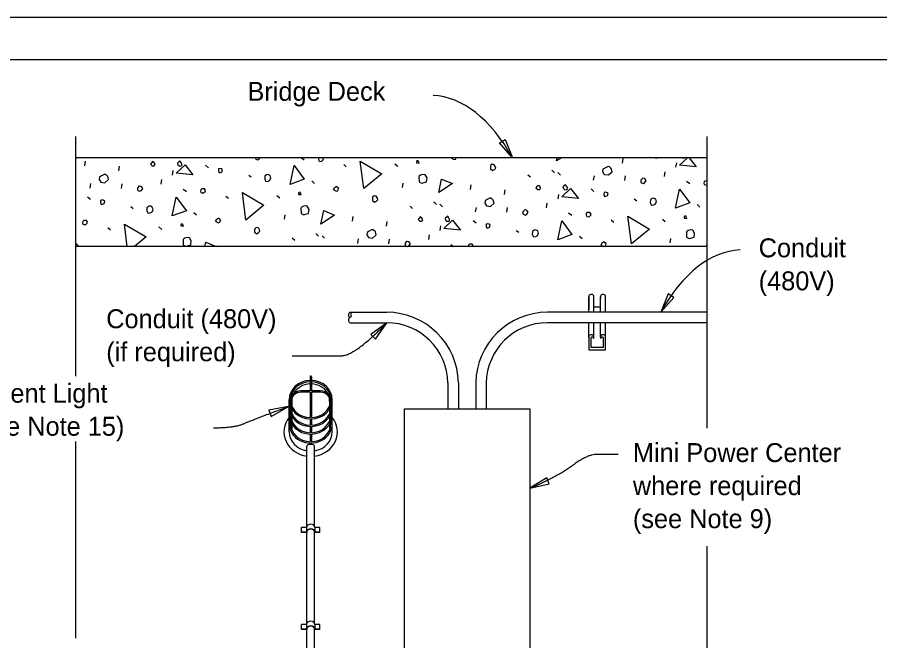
# Model space of a CAD drawing. Extents: x 0 to 30.8, y 0 to 21.2.
# Drawn here: x 12.47 to 19.36, y 14.82 to 19.8 of the extents above; entities that cross this region are included whole.
import ezdxf

# ---------------------------------------------------------------- set-up
doc = ezdxf.new("R2010")
doc.units = 0
for name, color, linetype in [('ActivePts-ConstElements', 7, 'Continuous'), ('Dimension', 7, 'Continuous'), ('Lighting', 7, 'Continuous'), ('Miscellaneous', 7, 'Continuous'), ('Miscellaneous1', 7, 'Continuous'), ('SteelGirder', 7, 'Continuous'), ('SupstrConc', 7, 'Continuous'), ('TextStructures', 7, 'Continuous')]:
    doc.layers.add(name, color=color, linetype=linetype)

msp = doc.modelspace()

# ---------------------------------------------------------------- linework, layer by layer
at = {"layer": 'ActivePts-ConstElements'}
msp.add_lwpolyline([(0, 0), (30.7879, 0), (30.7879, 19.4596), (0, 19.4596)], close=True, dxfattribs=at)
at = {"layer": 'Dimension'}
for points in [[(12.9354, 16.9316), (12.9354, 18.846)], [(17.9781, 16.5154), (17.9781, 18.846)], [(12.9354, 14.8369), (12.9354, 16.4094)], [(17.9781, 9.9617), (17.9781, 14.3999), (17.9006, 14.3999), (17.9781, 14.4336), (18.0556, 14.4674), (17.9781, 14.4674), (17.9781, 15.572)]]:
    msp.add_lwpolyline(points, dxfattribs=at)
for points in [[(16.4238, 18.6763), (16.3192, 18.7952), (16.3642, 18.8231)], [(17.6075, 17.442), (17.7122, 17.561), (17.6672, 17.5888)], [(15.4188, 17.3588), (15.2914, 17.2647), (15.3295, 17.228)], [(14.6337, 16.6891), (14.478, 16.6599), (14.4963, 16.6102)], [(16.563, 16.0355), (16.7173, 16.0714), (16.6968, 16.1202)]]:
    msp.add_lwpolyline(points, close=True, dxfattribs=at)
for centre, major_axis, start_param, end_param in [((15.6787, 16.8075), (-0.1111, -2.3674), 2.502126, 3.141581), ((18.3527, 15.5732), (0.1111, -2.3674), 3.141604, 3.781128)]:
    msp.add_ellipse(centre, major_axis=major_axis, ratio=0.464296, start_param=start_param, end_param=end_param, dxfattribs=at)
for points in [[(14.6643, 17.0949), (14.9501, 17.0949), (15.1645, 17.0949), (15.4188, 17.3588)], [(14.0365, 16.5193), (14.2049, 16.5193), (14.353, 16.5856), (14.6337, 16.689)], [(17.2673, 16.3061), (17.1601, 16.3061), (17.0223, 16.3061), (16.7824, 16.1274), (16.563, 16.0355)]]:
    msp.add_open_spline(points, degree=2, dxfattribs=at)
at = {"layer": 'Lighting'}
for p, q in [((17.0324, 17.442), (17.0324, 17.567)), ((17.0324, 17.567), (17.0324, 17.4644)), ((17.074, 17.5713), (17.0719, 17.5752)), ((17.074, 17.5553), (17.074, 17.5713)), ((17.074, 17.442), (17.074, 17.567)), ((17.1284, 17.5752), (17.1262, 17.5713)), ((17.1262, 17.5713), (17.1262, 17.5553)), ((17.1262, 17.442), (17.1262, 17.567)), ((17.1678, 17.442), (17.1678, 17.567)), ((15.1248, 17.442), (15.4188, 17.442)), ((17.9781, 17.442), (16.7034, 17.442)), ((17.1262, 17.483), (17.074, 17.483)), ((15.1245, 17.3588), (15.4188, 17.3588)), ((17.9781, 17.3588), (16.7034, 17.3588)), ((17.0324, 17.2441), (17.0324, 17.3588)), ((17.074, 17.2441), (17.074, 17.3588)), ((17.1262, 17.2441), (17.1262, 17.3588)), ((17.1678, 17.2441), (17.1678, 17.3588)), ((17.0324, 17.2441), (17.0324, 17.1415)), ((17.0532, 17.1601), (17.0532, 17.2398)), ((17.0621, 17.2431), (17.074, 17.2324)), ((17.074, 17.2484), (17.0719, 17.2523)), ((17.074, 17.2324), (17.074, 17.2484)), ((17.1284, 17.2523), (17.1262, 17.2484)), ((17.1262, 17.2484), (17.1262, 17.2324)), ((17.1262, 17.2324), (17.1382, 17.2431)), ((17.147, 17.2398), (17.147, 17.1601)), ((17.1678, 17.1415), (17.1678, 17.2441)), ((17.147, 17.1601), (17.0532, 17.1601)), ((17.0324, 17.1415), (17.1678, 17.1415)), ((14.8068, 16.9276), (14.8068, 16.8137)), ((14.8172, 16.9276), (14.8172, 16.8137)), ((15.9083, 16.8779), (15.9083, 16.6696)), ((15.9916, 16.8786), (15.9916, 16.6696)), ((16.1306, 16.8786), (16.1306, 16.6696)), ((16.2139, 16.8779), (16.2139, 16.6696)), ((14.8068, 16.8137), (14.7338, 16.8137)), ((14.8901, 16.8137), (14.8172, 16.8137)), ((14.6401, 16.4862), (14.6401, 16.7436)), ((14.8068, 16.8033), (14.7338, 16.8033)), ((14.8068, 16.8033), (14.8068, 16.6002)), ((14.8172, 16.8033), (14.8172, 16.6002)), ((14.8901, 16.8033), (14.8172, 16.8033)), ((14.9838, 16.4862), (14.9838, 16.7436)), ((14.6505, 16.6833), (14.6505, 16.6909)), ((14.9734, 16.6833), (14.9734, 16.6909)), ((14.6505, 16.623), (14.6505, 16.6306)), ((14.9734, 16.623), (14.9734, 16.6306)), ((14.6505, 16.5511), (14.6505, 16.5702)), ((14.8068, 16.5898), (14.8068, 16.5399)), ((14.8172, 16.5898), (14.8172, 16.5399)), ((14.9734, 16.5511), (14.9734, 16.5702)), ((14.8068, 16.5295), (14.8068, 16.4796)), ((14.8068, 16.4692), (14.8068, 16.4077)), ((14.8172, 16.5295), (14.8172, 16.4796)), ((14.8172, 16.4692), (14.8172, 16.4077)), ((14.7808, 15.7319), (14.7808, 16.372)), ((14.8432, 15.7319), (14.8432, 16.372)), ((14.7808, 14.9569), (14.7808, 15.6821)), ((14.8432, 14.9569), (14.8432, 15.6821)), ((14.7808, 14.1436), (14.7808, 14.9071)), ((14.8432, 14.1436), (14.8432, 14.9071))]:
    msp.add_line(p, q, dxfattribs=at)
msp.add_lwpolyline([(15.6966, 13.9446), (15.5611, 13.9446), (15.5611, 16.6696), (16.5611, 16.6696), (16.5611, 13.9446), (16.4256, 13.9446)], dxfattribs=at)
for centre, radius, start, end in [((15.1364, 17.4212), 0.0238, 119.00256, 240.99732), ((15.1133, 17.4212), 0.0238, 299.0029, 60.99699), ((15.4188, 16.8692), 0.5729, 0.94353, 90), ((16.7034, 16.8692), 0.5729, 90, 179.05647), ((15.1364, 17.3795), 0.0238, 119.00268, 240.02058), ((15.4188, 16.8692), 0.4896, 1.02064, 90), ((16.7034, 16.8692), 0.4896, 90, 178.97936), ((14.812, 16.9276), 0.0052, 0.05843, 180.0007), ((14.7338, 16.72), 0.0937, 90, 180), ((14.8901, 16.72), 0.0937, 0, 90), ((14.7338, 16.72), 0.0833, 90, 172.73922), ((14.8901, 16.72), 0.0833, 7.26127, 90)]:
    msp.add_arc(centre, radius, start, end, dxfattribs=at)
for centre, major_axis, ratio, start_param, end_param in [((17.0532, 17.567), (-0.0208, 0), 0.8951, 3.598509, 6.283184), ((17.147, 17.567), (0.0208, 0), 0.8951, 0.000002, 2.684677), ((17.0532, 17.2441), (-0.0208, 0), 0.8951, 3.598509, 6.283184), ((17.0584, 17.2398), (-0.0052, 0), 0.8951, 3.926991, 6.283185), ((17.147, 17.2441), (0.0208, 0), 0.8951, 0.000002, 2.684677), ((17.1418, 17.2398), (0.0052, 0), 0.8951, 6.283185, 8.63938), ((14.812, 16.7436), (-0.1718, 0), 0.895384, 4.742653, 7.823718), ((14.812, 16.7436), (-0.1614, 0), 0.888645, 4.744603, 6.130919), ((14.812, 16.7436), (-0.1718, 0), 0.895384, 3.141593, 4.682125), ((14.812, 16.7436), (-0.1614, 0), 0.888645, 3.306024, 4.680175), ((14.812, 16.7436), (-0.1718, 0), 0.895384, 1.60106, 3.141593), ((14.812, 16.6833), (-0.1718, 0), 0.895384, 0, 1.540533), ((14.812, 16.6833), (-0.1614, 0), 0.888645, 0.000093, 1.538583), ((14.812, 16.7436), (-0.1614, 0), 0.888645, 0.090994, 1.538583), ((14.812, 16.7436), (-0.1614, 0), 0.888645, 1.60301, 3.050599), ((14.812, 16.6833), (-0.1718, 0), 0.895384, 1.60106, 3.141593), ((14.812, 16.6833), (-0.1614, 0), 0.888645, 1.60301, 3.141686), ((14.812, 16.4862), (-0.2135, 0), 0.915812, 5.647609, 7.707355), ((14.812, 16.623), (-0.1718, 0), 0.895384, 0, 1.540533), ((14.812, 16.623), (-0.1614, 0), 0.888645, 0.000093, 1.538583), ((14.812, 16.623), (-0.1614, 0), 0.888645, 1.60301, 3.141686), ((14.812, 16.623), (-0.1718, 0), 0.895384, 1.60106, 3.141593), ((14.812, 16.4862), (-0.2135, 0), 0.915812, 1.717423, 3.777169), ((14.812, 16.5511), (-0.1718, 0), 0.895384, 0, 3.141593), ((14.812, 16.5511), (-0.1614, 0), 0.888645, 0.000093, 1.538583), ((14.812, 16.5511), (-0.1614, 0), 0.888645, 1.60301, 3.141686), ((14.812, 16.4862), (-0.1718, 0), 0.895384, 6.283173, 7.671415), ((14.812, 16.4862), (-0.1718, 0), 0.895384, 1.753362, 3.141593), ((14.812, 16.372), (-0.0312, 0), 0.446008, 3.14248, 6.283159)]:
    msp.add_ellipse(centre, major_axis=major_axis, ratio=ratio, start_param=start_param, end_param=end_param, dxfattribs=at)
at = {"layer": 'Miscellaneous'}
for p, q in [((14.7387, 18.6764), (14.7605, 18.6604)), ((17.0289, 18.6755), (17.029, 18.6764)), ((17.3013, 18.6346), (17.3067, 18.6723)), ((13.0081, 18.6127), (13.0136, 18.6504)), ((13.2805, 18.5718), (13.2859, 18.6095)), ((13.9723, 18.6174), (13.9956, 18.5978)), ((15.0759, 18.6232), (15.0962, 18.6054)), ((15.4833, 18.6289), (15.5067, 18.6093)), ((17.7293, 18.6018), (17.7354, 18.6371)), ((13.7086, 18.539), (13.7147, 18.5743)), ((14.3168, 18.5389), (14.3365, 18.5235)), ((16.5472, 18.5413), (16.5675, 18.5234)), ((16.737, 18.5766), (16.758, 18.5563)), ((16.7859, 18.5586), (16.8068, 18.5384)), ((17.0713, 18.4979), (17.0774, 18.5332)), ((17.3206, 18.4948), (17.326, 18.5325)), ((17.6378, 18.5281), (17.6432, 18.5658)), ((13.0505, 18.4351), (13.0566, 18.4704)), ((13.2998, 18.4321), (13.3053, 18.4698)), ((13.617, 18.4653), (13.6225, 18.503)), ((14.8209, 18.4928), (14.8419, 18.4726)), ((15.5447, 18.4383), (15.5508, 18.4736)), ((17.8137, 18.4898), (17.8395, 18.4708)), ((13.7929, 18.427), (13.8187, 18.408)), ((16.0871, 18.4232), (16.0925, 18.4608)), ((16.3595, 18.3823), (16.3649, 18.4199)), ((17.0513, 18.4279), (17.0746, 18.4082)), ((13.0305, 18.3651), (13.0539, 18.3454)), ((14.1341, 18.3709), (14.1544, 18.353)), ((14.5415, 18.3765), (14.5649, 18.3569)), ((16.7876, 18.3494), (16.7936, 18.3847)), ((17.3958, 18.3494), (17.4155, 18.3339)), ((13.3751, 18.2866), (13.3947, 18.2711)), ((15.6054, 18.2889), (15.6258, 18.2711)), ((15.7953, 18.3243), (15.8162, 18.304)), ((15.8441, 18.3063), (15.865, 18.286)), ((16.1295, 18.2456), (16.1356, 18.2809)), ((16.3788, 18.2425), (16.3842, 18.2802)), ((16.696, 18.2757), (16.7014, 18.3134)), ((17.8999, 18.3033), (17.9209, 18.283)), ((13.8792, 18.2405), (13.9001, 18.2202)), ((14.6029, 18.1859), (14.609, 18.2212)), ((15.1453, 18.1708), (15.1508, 18.2085)), ((16.8719, 18.2375), (16.8977, 18.2185)), ((17.6205, 18.187), (17.6439, 18.1674)), ((13.1923, 18.1185), (13.2126, 18.1007)), ((13.5997, 18.1242), (13.6231, 18.1046)), ((15.4177, 18.1299), (15.4231, 18.1676)), ((15.8458, 18.0971), (15.8519, 18.1324)), ((16.1095, 18.1755), (16.1328, 18.1559)), ((17.2131, 18.1813), (17.2334, 18.1635)), ((14.8535, 18.0719), (14.8744, 18.0516)), ((14.9023, 18.0539), (14.9233, 18.0337)), ((15.7542, 18.0234), (15.7597, 18.0611)), ((16.454, 18.097), (16.4737, 18.0816)), ((16.9581, 18.0509), (16.9791, 18.0306)), ((12.9374, 17.9881), (12.9582, 17.968)), ((14.6637, 18.0366), (14.684, 18.0187)), ((15.1877, 17.9932), (15.1938, 18.0285)), ((15.437, 17.9902), (15.4425, 18.0278)), ((15.9301, 17.9851), (15.9534, 17.968)), ((17.6819, 17.9964), (17.688, 18.0317)), ((13.6671, 17.968), (13.6672, 17.9689)), ((14.661, 16.7297), (14.661, 16.6927)), ((14.963, 16.7297), (14.963, 16.6927)), ((14.661, 16.67), (14.661, 16.6324)), ((14.661, 16.6097), (14.661, 16.5721)), ((14.963, 16.67), (14.963, 16.6324)), ((14.963, 16.6097), (14.963, 16.5721)), ((14.661, 16.5494), (14.661, 16.5002)), ((14.963, 16.5494), (14.963, 16.5002))]:
    msp.add_line(p, q, dxfattribs=at)
for points in [[(14.3699, 18.6764), (14.3698, 18.6696), (14.3875, 18.6614), (14.4014, 18.6677), (14.4075, 18.6764)], [(14.8797, 18.6764), (14.8761, 18.6733), (14.8739, 18.6623), (14.8765, 18.6526)], [(14.8765, 18.6526), (14.8826, 18.6491), (14.8984, 18.6482), (14.9109, 18.6593), (14.9138, 18.6678), (14.9081, 18.6764)], [(15.9378, 18.6764), (15.9374, 18.6729), (15.9364, 18.6764)], [(15.9374, 18.6729), (15.9557, 18.6623), (15.9702, 18.6662), (15.9729, 18.6764)], [(16.7764, 18.6519), (16.7817, 18.6764)], [(16.8146, 18.6764), (16.7764, 18.6519)], [(17.5659, 18.6764), (17.5674, 18.6749), (17.5825, 18.6763), (17.5826, 18.6764)], [(17.7588, 18.6174), (17.8222, 18.6764)], [(17.8344, 18.6764), (17.8918, 18.6039), (17.7588, 18.6174)], [(17.7809, 18.6764), (17.7821, 18.6754), (17.7954, 18.6738), (17.7983, 18.6764)], [(13.5325, 18.6264), (13.5467, 18.6121), (13.5618, 18.6135), (13.5695, 18.6234), (13.5682, 18.6282), (13.5595, 18.6414), (13.5479, 18.6461), (13.5402, 18.6362), (13.5325, 18.6264)], [(13.738, 18.5547), (13.8085, 18.6201), (13.8711, 18.5411), (13.738, 18.5547)], [(13.7515, 18.6204), (13.7613, 18.6127), (13.7747, 18.6111), (13.7831, 18.6185), (13.7829, 18.6288), (13.7772, 18.6402), (13.7692, 18.651), (13.756, 18.6423), (13.7476, 18.6349), (13.7515, 18.6204)], [(14.6474, 18.4644), (14.6794, 18.6154), (14.7607, 18.5051), (14.6474, 18.4644)], [(15.2362, 18.4307), (15.2082, 18.6509), (15.3803, 18.5495), (15.2362, 18.4307)], [(15.6572, 18.6367), (15.6785, 18.6346), (15.6759, 18.6443), (15.6678, 18.655), (15.657, 18.647), (15.6572, 18.6367)], [(16.2478, 18.606), (16.2475, 18.5878), (16.2641, 18.5741), (16.2797, 18.5835), (16.2898, 18.5939), (16.2866, 18.606), (16.2772, 18.6216), (16.2608, 18.625), (16.2482, 18.6139), (16.2478, 18.606)], [(17.1435, 18.5665), (17.1572, 18.5443), (17.1894, 18.5399), (17.2187, 18.5659), (17.2123, 18.5901), (17.195, 18.6061), (17.1823, 18.6053), (17.1618, 18.5947), (17.1462, 18.5853), (17.1435, 18.5665)], [(13.1228, 18.5037), (13.1365, 18.4815), (13.1687, 18.4772), (13.198, 18.5031), (13.1915, 18.5273), (13.1743, 18.5433), (13.1615, 18.5425), (13.1411, 18.5319), (13.1255, 18.5225), (13.1228, 18.5037)], [(14.0749, 18.5724), (14.0788, 18.558), (14.0915, 18.5588), (14.1029, 18.5644), (14.1087, 18.5815), (14.1019, 18.5875), (14.0903, 18.5921), (14.0759, 18.5882), (14.0749, 18.5724)], [(14.4462, 18.5296), (14.4447, 18.5059), (14.4547, 18.4879), (14.4723, 18.49), (14.4837, 18.4956), (14.4943, 18.514), (14.4885, 18.5357), (14.4708, 18.5439), (14.4587, 18.5407), (14.4462, 18.5296)], [(15.676, 18.5278), (15.6774, 18.4842), (15.6981, 18.4742), (15.7102, 18.4775), (15.7368, 18.4846), (15.7411, 18.5168), (15.7267, 18.5414), (15.7079, 18.5441), (15.6886, 18.539), (15.676, 18.5278)], [(15.8346, 18.3995), (15.8577, 18.5066), (15.945, 18.4705), (15.8346, 18.3995)], [(17.4491, 18.4982), (17.4488, 18.48), (17.4665, 18.4718), (17.4804, 18.4781), (17.4916, 18.4941), (17.4835, 18.5049), (17.4768, 18.5108), (17.4658, 18.5131), (17.461, 18.5118), (17.4491, 18.4982)], [(17.9781, 18.4914), (17.9635, 18.4911), (17.9551, 18.4837), (17.9529, 18.4727), (17.9554, 18.4631)], [(17.9554, 18.4631), (17.9616, 18.4595), (17.9774, 18.4586), (17.9781, 18.4593)], [(13.4283, 18.4354), (13.428, 18.4172), (13.4458, 18.409), (13.4596, 18.4153), (13.4709, 18.4313), (13.4628, 18.4421), (13.456, 18.448), (13.4451, 18.4503), (13.4402, 18.449), (13.4283, 18.4354)], [(13.9347, 18.4003), (13.9408, 18.3968), (13.9566, 18.3958), (13.9691, 18.4069), (13.972, 18.4155), (13.9633, 18.4287), (13.9427, 18.4283), (13.9343, 18.4209), (13.9321, 18.4099), (13.9347, 18.4003)], [(14.2944, 18.1783), (14.2664, 18.3986), (14.4385, 18.2972), (14.2944, 18.1783)], [(14.7154, 18.3843), (14.7367, 18.3822), (14.7341, 18.3919), (14.726, 18.4027), (14.7153, 18.3946), (14.7154, 18.3843)], [(14.9956, 18.4206), (15.014, 18.41), (15.0285, 18.4138), (15.0336, 18.4333), (15.0146, 18.4464), (15.0062, 18.4389), (14.9972, 18.4339), (14.9956, 18.4206), (14.9943, 18.4254)], [(16.6114, 18.4368), (16.6256, 18.4225), (16.6408, 18.424), (16.6485, 18.4338), (16.6472, 18.4386), (16.6385, 18.4518), (16.6269, 18.4565), (16.6192, 18.4467), (16.6114, 18.4368)], [(16.817, 18.3651), (16.8875, 18.4306), (16.95, 18.3516), (16.817, 18.3651)], [(16.8305, 18.4308), (16.8403, 18.4231), (16.8537, 18.4215), (16.862, 18.4289), (16.8619, 18.4392), (16.8562, 18.4507), (16.8481, 18.4614), (16.8349, 18.4527), (16.8266, 18.4453), (16.8305, 18.4308)], [(17.1539, 18.3829), (17.1578, 18.3684), (17.1705, 18.3692), (17.1819, 18.3749), (17.1877, 18.3919), (17.1809, 18.3979), (17.1693, 18.4026), (17.1548, 18.3987), (17.1539, 18.3829)], [(17.7263, 18.2749), (17.7584, 18.4258), (17.8397, 18.3156), (17.7263, 18.2749)], [(13.1331, 18.3201), (13.137, 18.3056), (13.1497, 18.3064), (13.1612, 18.3121), (13.1669, 18.3292), (13.1602, 18.3351), (13.1486, 18.3398), (13.1341, 18.3359), (13.1331, 18.3201)], [(13.7056, 18.2121), (13.7376, 18.363), (13.8189, 18.2528), (13.7056, 18.2121)], [(15.306, 18.3536), (15.3057, 18.3354), (15.3223, 18.3218), (15.3379, 18.3311), (15.348, 18.3416), (15.3448, 18.3537), (15.3354, 18.3693), (15.319, 18.3726), (15.3065, 18.3615), (15.306, 18.3536)], [(16.2017, 18.3141), (16.2155, 18.2919), (16.2477, 18.2876), (16.2769, 18.3136), (16.2705, 18.3377), (16.2532, 18.3538), (16.2405, 18.353), (16.2201, 18.3423), (16.2045, 18.333), (16.2017, 18.3141)], [(17.5251, 18.34), (17.5237, 18.3163), (17.5337, 18.2983), (17.5513, 18.3004), (17.5627, 18.3061), (17.5733, 18.3244), (17.5675, 18.3462), (17.5498, 18.3544), (17.5377, 18.3511), (17.5251, 18.34)], [(13.5044, 18.2772), (13.503, 18.2536), (13.513, 18.2355), (13.5305, 18.2376), (13.5419, 18.2433), (13.5525, 18.2617), (13.5467, 18.2834), (13.529, 18.2916), (13.5169, 18.2884), (13.5044, 18.2772)], [(14.7342, 18.2755), (14.7356, 18.2318), (14.7564, 18.2219), (14.7684, 18.2251), (14.795, 18.2322), (14.7993, 18.2644), (14.785, 18.2891), (14.7661, 18.2918), (14.7468, 18.2866), (14.7342, 18.2755)], [(16.5073, 18.2459), (16.507, 18.2277), (16.5247, 18.2195), (16.5386, 18.2258), (16.5498, 18.2417), (16.5418, 18.2525), (16.535, 18.2585), (16.524, 18.2607), (16.5192, 18.2594), (16.5073, 18.2459)], [(14.0538, 18.1682), (14.0722, 18.1576), (14.0867, 18.1615), (14.0918, 18.181), (14.0728, 18.194), (14.0644, 18.1866), (14.0554, 18.1816), (14.0538, 18.1682), (14.0525, 18.173)], [(14.8929, 18.1472), (14.9159, 18.2543), (15.0032, 18.2181), (14.8929, 18.1472)], [(15.6697, 18.1845), (15.6839, 18.1702), (15.699, 18.1716), (15.7067, 18.1815), (15.7054, 18.1863), (15.6967, 18.1995), (15.6851, 18.2041), (15.6774, 18.1943), (15.6697, 18.1845)], [(15.8887, 18.1785), (15.8985, 18.1707), (15.9119, 18.1692), (15.9203, 18.1766), (15.9201, 18.1869), (15.9144, 18.1983), (15.9064, 18.2091), (15.8932, 18.2004), (15.8848, 18.193), (15.8887, 18.1785)], [(17.0137, 18.2107), (17.0198, 18.2072), (17.0356, 18.2062), (17.0481, 18.2174), (17.051, 18.2259), (17.0423, 18.2391), (17.0217, 18.2388), (17.0133, 18.2313), (17.0111, 18.2204), (17.0137, 18.2107)], [(17.3734, 17.9888), (17.3454, 18.209), (17.5175, 18.1076), (17.3734, 17.9888)], [(17.7944, 18.1948), (17.8157, 18.1927), (17.8131, 18.2023), (17.805, 18.2131), (17.7942, 18.2051), (17.7944, 18.1948)], [(12.9929, 18.1479), (12.999, 18.1444), (13.0148, 18.1435), (13.0274, 18.1546), (13.0303, 18.1631), (13.0215, 18.1763), (13.0009, 18.176), (12.9926, 18.1686), (12.9903, 18.1576), (12.9929, 18.1479)], [(13.3473, 17.968), (13.3247, 18.1462), (13.4968, 18.0448), (13.4035, 17.968)], [(13.7737, 18.132), (13.7949, 18.1299), (13.7923, 18.1396), (13.7843, 18.1503), (13.7735, 18.1423), (13.7737, 18.132)], [(14.3642, 18.1013), (14.3639, 18.0831), (14.3805, 18.0694), (14.3961, 18.0788), (14.4063, 18.0892), (14.403, 18.1013), (14.3937, 18.1169), (14.3772, 18.1203), (14.3647, 18.1092), (14.3642, 18.1013)], [(15.8752, 18.1127), (15.9457, 18.1782), (16.0083, 18.0992), (15.8752, 18.1127)], [(16.2121, 18.1305), (16.216, 18.116), (16.2287, 18.1169), (16.2401, 18.1225), (16.2459, 18.1396), (16.2391, 18.1455), (16.2275, 18.1502), (16.2131, 18.1463), (16.2121, 18.1305)], [(16.7846, 18.0225), (16.8166, 18.1735), (16.8979, 18.0632), (16.7846, 18.0225)], [(15.26, 18.0618), (15.2737, 18.0396), (15.3059, 18.0352), (15.3352, 18.0612), (15.3287, 18.0854), (15.3115, 18.1014), (15.2987, 18.1006), (15.2783, 18.09), (15.2627, 18.0806), (15.26, 18.0618)], [(16.5834, 18.0877), (16.5819, 18.064), (16.5919, 18.046), (16.6095, 18.0481), (16.6209, 18.0537), (16.6315, 18.0721), (16.6257, 18.0938), (16.608, 18.102), (16.5959, 18.0988), (16.5834, 18.0877)], [(17.8132, 18.0859), (17.8146, 18.0423), (17.8353, 18.0323), (17.8474, 18.0356), (17.874, 18.0427), (17.8783, 18.0749), (17.8639, 18.0995), (17.8451, 18.1022), (17.8258, 18.097), (17.8132, 18.0859)], [(13.7925, 18.0231), (13.7938, 17.9795), (13.8146, 17.9695), (13.8267, 17.9728), (13.8532, 17.9799), (13.8575, 18.0121), (13.8432, 18.0367), (13.8243, 18.0394), (13.805, 18.0343), (13.7925, 18.0231)], [(13.9668, 17.968), (13.9741, 18.0019), (14.0562, 17.968)], [(15.5655, 17.9935), (15.5652, 17.9753), (15.5812, 17.968)], [(15.5848, 17.968), (15.5968, 17.9734), (15.6081, 17.9894), (15.6, 18.0002), (15.5932, 18.0061), (15.5823, 18.0084), (15.5774, 18.0071), (15.5655, 17.9935)], [(16.1073, 17.968), (16.1092, 17.9736), (16.1005, 17.9868), (16.0799, 17.9864), (16.0715, 17.979), (16.0693, 17.968), (16.0693, 17.968)], [(17.1328, 17.9787), (17.1512, 17.968), (17.1657, 17.9719), (17.1708, 17.9914), (17.1518, 18.0044), (17.1434, 17.997), (17.1344, 17.992), (17.1328, 17.9787), (17.1315, 17.9835)], [(17.9741, 17.968), (17.9781, 17.9868)]]:
    msp.add_lwpolyline(points, dxfattribs=at)
for start_param, end_param in [(1.605229, 2.691201), (0.45306, 1.536364), (2.896336, 3.176025), (6.248753, 6.522968)]:
    msp.add_ellipse((14.812, 16.7343), major_axis=(0.151, 0), ratio=0.895384, start_param=start_param, end_param=end_param, dxfattribs=at)
at = {"layer": 'Miscellaneous1'}
msp.add_lwpolyline([(0, 19.8), (30.8, 19.8), (30.8, 0), (0, 0)], close=True, dxfattribs=at)
at = {"layer": 'SteelGirder'}
for p, q in [((14.7785, 15.7217), (14.7391, 15.7217)), ((14.7391, 15.6821), (14.7391, 15.7217)), ((14.7785, 15.7217), (14.7785, 15.6844)), ((14.8849, 15.7217), (14.8455, 15.7217)), ((14.8455, 15.7217), (14.8455, 15.6844)), ((14.8849, 15.6821), (14.8849, 15.7217)), ((14.7785, 15.6844), (14.7391, 15.6844)), ((14.7808, 15.6821), (14.7391, 15.6821)), ((14.8849, 15.6821), (14.8432, 15.6821)), ((14.8849, 15.6844), (14.8455, 15.6844)), ((14.7785, 14.9468), (14.7391, 14.9468)), ((14.7391, 14.9071), (14.7391, 14.9468)), ((14.7785, 14.9095), (14.7391, 14.9095)), ((14.7808, 14.9071), (14.7391, 14.9071)), ((14.7785, 14.9468), (14.7785, 14.9095)), ((14.8849, 14.9071), (14.8432, 14.9071)), ((14.8849, 14.9468), (14.8455, 14.9468)), ((14.8455, 14.9468), (14.8455, 14.9095)), ((14.8849, 14.9095), (14.8455, 14.9095)), ((14.8849, 14.9071), (14.8849, 14.9468))]:
    msp.add_line(p, q, dxfattribs=at)
for centre, major_axis, ratio, end_param in [((14.812, 15.7217), (-0.0335, 0), 0.830773, 6.282753), ((14.812, 15.6844), (-0.0335, 0), 0.830773, 6.282753), ((14.812, 15.6821), (-0.0312, 0), 0.892016, 6.283768), ((14.812, 14.9468), (-0.0335, 0), 0.830773, 6.282753), ((14.812, 14.9095), (-0.0335, 0), 0.830773, 6.282753), ((14.812, 14.9071), (-0.0312, 0), 0.892016, 6.283768)]:
    msp.add_ellipse(centre, major_axis=major_axis, ratio=ratio, start_param=3.141593, end_param=end_param, dxfattribs=at)
at = {"layer": 'SupstrConc'}
for p, q in [((17.9781, 18.6764), (12.9354, 18.6764)), ((17.9781, 17.968), (12.9354, 17.968))]:
    msp.add_line(p, q, dxfattribs=at)

# ---------------------------------------------------------------- texts
at = {"layer": 'Dimension'}
for s, p in [('Conduit', (18.39, 17.8817)), ('(480V)', (18.39, 17.6177)), ('Conduit (480V)', (13.1788, 17.3149)), ('(if required)', (13.1788, 17.0509)), ('Incandescent Light', (11.4918, 16.7198)), ('fixture (see Note 15)', (11.4918, 16.4558)), ('Mini Power Center', (17.3853, 16.2452)), ('where required', (17.3853, 15.9812)), ('(see Note 9)', (17.3853, 15.7172))]:
    msp.add_text(s, height=0.1512, dxfattribs=at).set_placement(p)
at = {"layer": 'TextStructures'}
msp.add_text('Bridge Deck', height=0.1512, dxfattribs=at).set_placement((14.3069, 19.132))

doc.saveas('drawing.dxf')
